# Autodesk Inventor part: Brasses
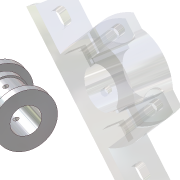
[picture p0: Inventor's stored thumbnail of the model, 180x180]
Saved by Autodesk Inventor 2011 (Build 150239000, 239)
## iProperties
Shininess: 77.0
Length Units: 11269
Angle Units: 11279
Time Units: 11290
Mass Units: 11283
Length Display Precision: 3
Angle Display Precision: 2
Created: 2002-02
Part Number: Brasses
Document SubType Name: Modeling
Designer: ***
Density: 1 g/cm^3
Density: 0.0
Volumn: 0.0
Area: 0.0
PropertySet Name: Model Information
Control State: 0
Master: False
Checked Out: False
Author: ***
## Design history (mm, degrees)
sketch "Sketch1"
  geometry: L1 (16.829, 46.472)-(48.829, 46.472); L2 (48.829, 46.472)-(48.829, 37.472); L3 (48.829, 37.472)-(40.829, 37.472); L4 (40.829, 37.472)-(40.829, 28.472); L5 (40.829, 28.472)-(38.829, 28.472); L6 (38.829, 28.472)-(38.829, 0.472); L7 (38.829, 0.472)-(40.829, 0.472); L8 (40.829, 0.472)-(40.829, -8.528); L9 (40.829, -8.528)-(48.829, -8.528); L10 (48.829, -8.528)-(48.829, -17.528); L11 (48.829, -17.528)-(16.829, -17.528); L12 (16.829, -17.528)-(16.829, 46.472)
  constraints: 24 end point, 9 parallel, 4 equal length, 1 collinear, 1 horizontal, 1 perpendicular
  dimensions: "d0" = 64 diameter of L2 L12; "d1" = 44 diameter of L6 L12; "d2" = 48 diameter of L8 L12; "d3" = 9 distance of L1.end L2.end; "d4" = 46 distance between parallel lines of L9 L3; "d5" = 28 distance of L5.end L6.end
revolve "Revolution1" sketch "Sketch1" stored, may be unused: angle "d7" = 90 deg
sketch "Sketch2"
  geometry: C1 r 32 at (0, 0) reference
hole "Hole1" sketch "Sketch2" at (0, 0) diameter "d8" = 32; stored, may be unused: countersink angle "d12" = 82 deg, drill point angle "d14" = 118 deg; dims "d9" = 6, "d10" = 4, "d11" = 2, "d13" = 8
workplane "Work Plane1"
workplane "Work Plane2"
sketch "Sketch3"
  geometry: L1 (-32, -32)-(32, -32) reference; C1 r 4 at (0, 0)
  constraints: 1 centre point
  dimensions: "d16" = 8 diameter of C1; "d17" = 32 distance from line of L1 C1.centre
extrude "Extrusion1" join sketch "Sketch3" stored distance "d18" = 10; taper "d19" = 0 deg
sketch "Sketch4"
  geometry: C1 r 4 at (0, 0) reference
hole "Hole2" sketch "Sketch4" at (0, 0) diameter "d20" = 6; stored, may be unused: countersink angle "d24" = 82 deg, drill point angle "d26" = 118 deg; dims "d21" = 6, "d22" = 4, "d23" = 2, "d25" = 8
body "Solid1"
other parameters: "d15" = -52
